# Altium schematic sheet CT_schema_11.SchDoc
size 274 x 160 mm
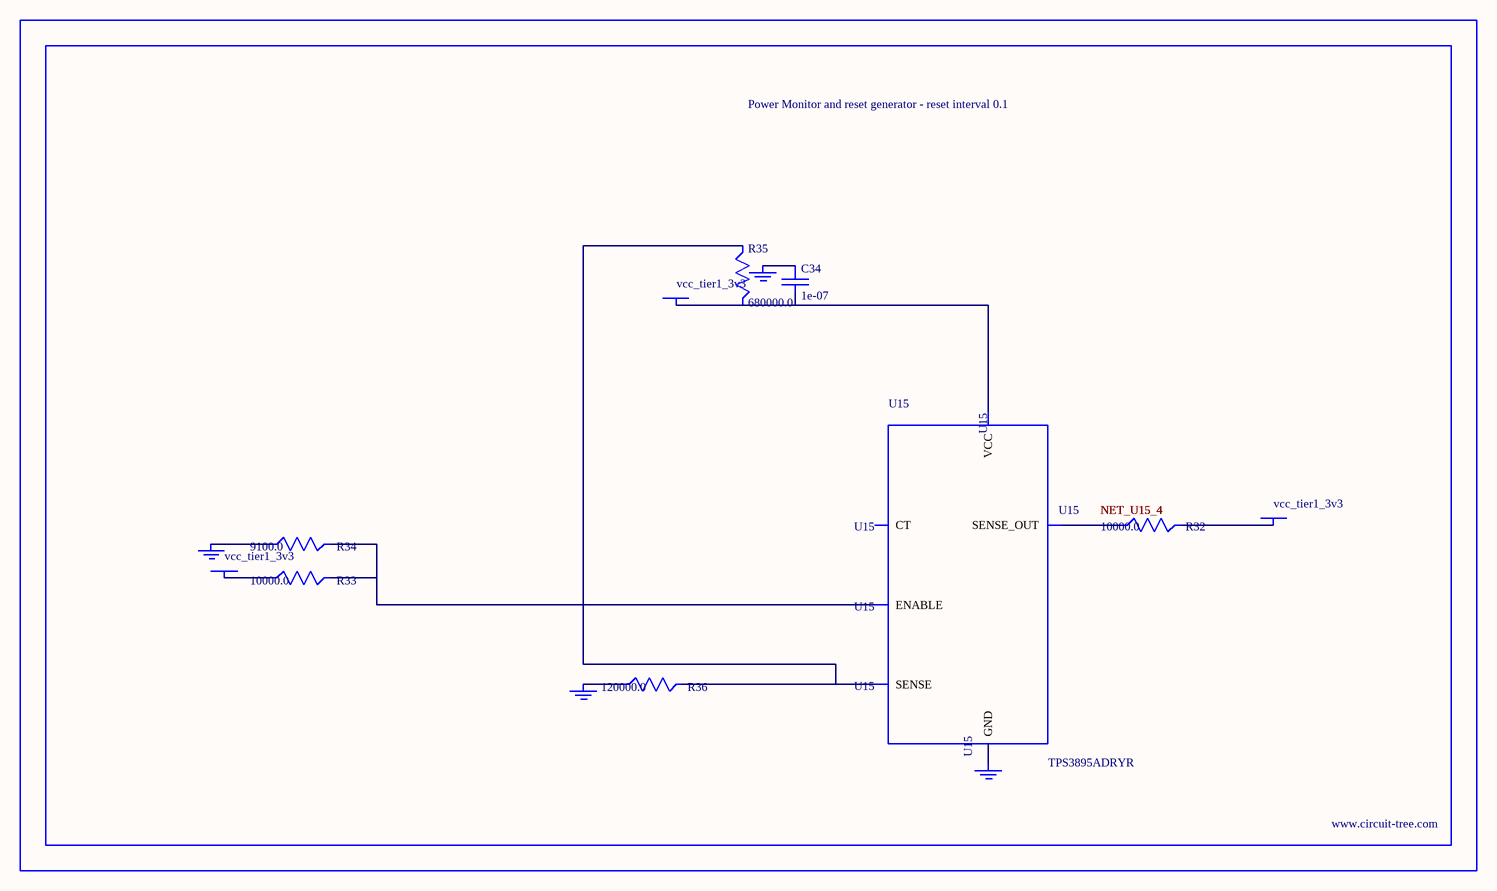
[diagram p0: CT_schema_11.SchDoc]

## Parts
BORDER10  (no value)
C34  1e-07  [C0402]
GND_INSTANCE_10_0  (no value)
GND_INSTANCE_10_1  (no value)
GND_INSTANCE_10_2  (no value)
GND_INSTANCE_10_3  (no value)
POWER_INSTANCE_10_0  vcc_tier1_3v3
POWER_INSTANCE_10_1  vcc_tier1_3v3
POWER_INSTANCE_10_2  vcc_tier1_3v3
R32  10000.0  [R0603]
R33  10000.0  [R0603]
R34  9100.0  [R0603]
R35  680000.0  [R0603]
R36  120000.0  [R0603]
U15  TPS3895ADRYR  [SON-6]

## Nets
NetC34_1: C34.1 GND_INSTANCE_10_2.0(GND)
NetC34_2: C34.2 POWER_INSTANCE_10_2.0(PWR) R35.2 U15.6(VCC)
NetGND_INSTANCE_10_0_0: GND_INSTANCE_10_0.0(GND) R34.1
NetGND_INSTANCE_10_1_0: GND_INSTANCE_10_1.0(GND) R36.1
NetGND_INSTANCE_10_3_0: GND_INSTANCE_10_3.0(GND) U15.2(GND)
NetPOWER_INSTANCE_10_0_0: POWER_INSTANCE_10_0.0(PWR) R33.1
NetPOWER_INSTANCE_10_1_0: POWER_INSTANCE_10_1.0(PWR) R32.2
NetR32_1: R32.1 U15.4(SENSE_OUT)
NetR33_2: R33.2 R34.2 U15.1(ENABLE)
NetR35_1: R35.1 R36.2 U15.3(SENSE)

Not connected (* = marked no-connect by the designer): U15 5(CT)

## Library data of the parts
BORDER10 = BORDER_PAGE10
C34 = C0402C104K3RACTU
GND_INSTANCE_10_0-GND_INSTANCE_10_3 = GND
POWER_INSTANCE_10_0-POWER_INSTANCE_10_2 = PWR
R32 R33 = RC0603JR-0710KL
R34 = RC0603JR-079K1L
R35 = RC0603JR-07680KL
R36 = RC0603JR-07120KL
